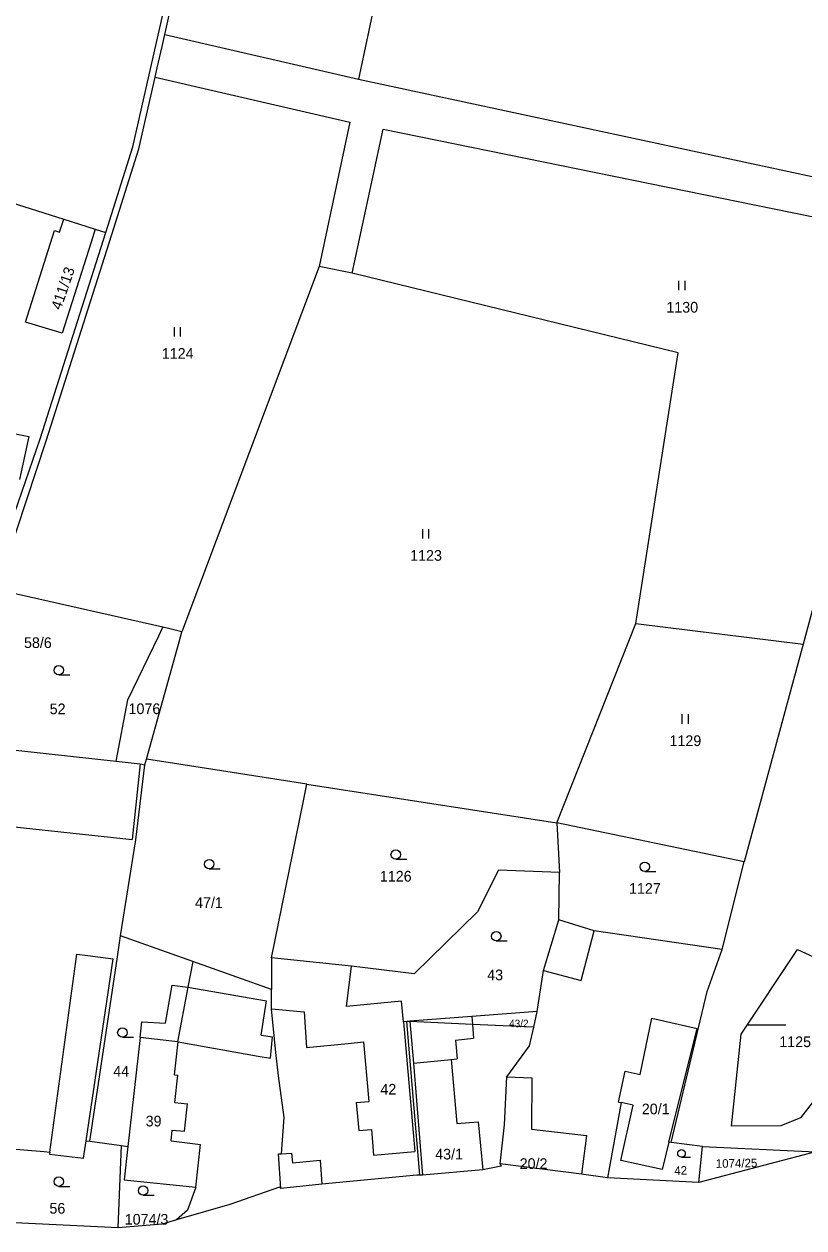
# Model space of a CAD drawing. Extents: x -746176 to -739709, y -1128407 to -1124482.
# Drawn here: x -742237.2 to -742113, y -1126052.3 to -1125860.6 of the extents above; entities that cross this region are included whole.
import ezdxf

# ---------------------------------------------------------------- set-up
doc = ezdxf.new("R2010")
doc.units = 0
for name, color, linetype in [('Hranice parcel', 7, 'Continuous'), ('Parcelní čísla', 7, 'Continuous'), ('Vnitřní kresba', 7, 'Continuous'), ('Značky kultur', 7, 'Continuous')]:
    doc.layers.add(name, color=color, linetype=linetype)

msp = doc.modelspace()

# ---------------------------------------------------------------- linework, layer by layer
at = {"layer": 'Hranice parcel'}
for p, q in [((-742144.45, -1125683.53), (-742183.95, -1125869.36)), ((-742214.78, -1125862.24), (-742205.45, -1125821.07)), ((-742214.78, -1125862.24), (-742183.95, -1125869.36)), ((-742183.95, -1125869.36), (-742094.09, -1125888.65)), ((-742251.35, -1125885.17), (-742230.88, -1125891.65)), ((-742230.88, -1125891.65), (-742225.86, -1125893.24)), ((-742225.86, -1125893.24), (-742224.19, -1125893.77)), ((-742190.21, -1125899.2), (-742212.05, -1125957.33)), ((-742184.93, -1125900.23), (-742190.21, -1125899.2)), ((-742110.2, -1125948.49), (-742113.1, -1125959.31)), ((-742215.07, -1125956.62), (-742241.51, -1125950.63)), ((-742152.36, -1125987.76), (-742139.76, -1125956.04)), ((-742139.76, -1125956.04), (-742113.1, -1125959.31)), ((-742113.1, -1125959.31), (-742122.54, -1125993.99)), ((-742246.94, -1125975.25), (-742222.55, -1125977.95)), ((-742217.96, -1125978.51), (-742217.71, -1125977.62)), ((-742192.16, -1125981.6), (-742152.36, -1125987.76)), ((-742122.54, -1125993.99), (-742152.36, -1125987.76)), ((-742152.36, -1125987.76), (-742151.94, -1125995.7)), ((-742126.05, -1126007.96), (-742122.54, -1125993.99)), ((-742152.03, -1126003.21), (-742151.94, -1125995.7)), ((-742210.31, -1126009.86), (-742221.81, -1126005.78)), ((-742197.78, -1126014.31), (-742210.31, -1126009.86)), ((-742197.79, -1126009.24), (-742197.78, -1126014.31)), ((-742174.18, -1126043.87), (-742176.24, -1126019.4)), ((-742156.03, -1126020.28), (-742155.5, -1126017.83)), ((-742156.03, -1126020.28), (-742165.79, -1126019.86)), ((-742226.7, -1126038.48), (-742221.69, -1126039.15)), ((-742129.13, -1126039.33), (-742134.12, -1126038.69)), ((-742222.2, -1126052.27), (-742221.69, -1126039.15)), ((-742221.69, -1126039.15), (-742220.66, -1126039.29)), ((-742129.74, -1126045.05), (-742129.13, -1126039.33)), ((-742111.14, -1126040.16), (-742129.74, -1126045.05)), ((-742129.13, -1126039.33), (-742111.14, -1126040.16)), ((-742148.42, -1126043.69), (-742161.35, -1126042.09)), ((-742144.3, -1126044.3), (-742148.42, -1126043.69)), ((-742129.74, -1126045.05), (-742144.3, -1126044.3))]:
    msp.add_line(p, q, dxfattribs=at)
for points in [[(-742224.19, -1125893.77), (-742219.86, -1125880.14), (-742206.44, -1125820.89)], [(-742216.33, -1125869.06), (-742215.99, -1125867.54), (-742215.21, -1125864.13), (-742214.78, -1125862.24)], [(-742241.51, -1125950.63), (-742233.66, -1125926.96), (-742223.23, -1125894.07), (-742218.91, -1125880.44), (-742217.69, -1125875.07), (-742216.33, -1125869.06)], [(-742216.33, -1125869.06), (-742185.29, -1125876.22), (-742190.21, -1125899.2)], [(-742184.93, -1125900.23), (-742180.03, -1125877.3), (-742095.09, -1125894.63)], [(-742225.86, -1125893.24), (-742226.52, -1125895.3), (-742231.11, -1125909.81), (-742236.97, -1125908.02), (-742232.36, -1125893.45), (-742231.54, -1125893.71), (-742230.88, -1125891.65)], [(-742239.87, -1125941.89), (-742234.61, -1125926.63), (-742224.19, -1125893.77)], [(-742139.76, -1125956.04), (-742133.02, -1125912.95), (-742184.93, -1125900.23)], [(-742261.6, -1125921.22), (-742236.44, -1125926.26), (-742237.93, -1125933.1)], [(-742222.55, -1125977.95), (-742220.67, -1125968.16), (-742215.73, -1125957.97), (-742215.07, -1125956.62)], [(-742217.71, -1125977.62), (-742212.49, -1125958.92), (-742212.05, -1125957.33)], [(-742212.05, -1125957.33), (-742213.99, -1125956.87), (-742215.07, -1125956.62)], [(-742222.55, -1125977.95), (-742218.7, -1125978.38), (-742217.96, -1125978.51)], [(-742221.81, -1126005.78), (-742219.41, -1125990.5), (-742217.96, -1125978.51)], [(-742192.16, -1125981.6), (-742212.57, -1125978.42), (-742217.71, -1125977.62)], [(-742197.79, -1126009.24), (-742192.7, -1125984.26), (-742192.16, -1125981.6)], [(-742151.94, -1125995.7), (-742161.62, -1125995.29), (-742165.01, -1126001.93), (-742175.08, -1126011.79), (-742185.07, -1126010.6)], [(-742155.5, -1126017.83), (-742154.46, -1126011.3), (-742152.03, -1126003.21)], [(-742126.05, -1126007.96), (-742146.39, -1126004.99), (-742152.03, -1126003.21)], [(-742226.7, -1126038.48), (-742222.39, -1126009.48), (-742221.81, -1126005.78)], [(-742134.12, -1126038.69), (-742128.4, -1126014.62), (-742126.05, -1126007.96)], [(-742102.49, -1126016.08), (-742109.85, -1126029.96), (-742113.56, -1126034.73), (-742116.68, -1126036.01), (-742124.54, -1126036.07), (-742122.99, -1126021.43), (-742114.02, -1126007.91), (-742106.36, -1126011.45), (-742102.49, -1126016.08)], [(-742210.31, -1126009.86), (-742211.09, -1126013.94), (-742212.75, -1126022.64), (-742218.71, -1126021.97), (-742220.66, -1126039.29)], [(-742185.07, -1126010.6), (-742196.8, -1126009.35), (-742197.79, -1126009.24)], [(-742176.24, -1126019.4), (-742176.77, -1126019.44), (-742177.07, -1126016.16), (-742185.84, -1126017), (-742185.07, -1126010.6)], [(-742196.32, -1126046.01), (-742196.68, -1126040.49), (-742196.21, -1126040.46), (-742195.76, -1126034.69), (-742196.68, -1126028.06), (-742197.1, -1126024.33), (-742197.78, -1126017.4), (-742197.78, -1126014.31)], [(-742155.5, -1126017.83), (-742165.88, -1126018.63), (-742175.74, -1126019.37), (-742176.24, -1126019.4)], [(-742165.79, -1126019.86), (-742175.74, -1126019.42), (-742176.24, -1126019.4)], [(-742160.34, -1126028.23), (-742156.69, -1126023.3), (-742156.03, -1126020.28)], [(-742161.35, -1126042.09), (-742160.66, -1126035.86), (-742160.34, -1126028.23)], [(-742160.34, -1126028.23), (-742156.31, -1126028.36), (-742156.37, -1126036.56), (-742147.63, -1126037.55), (-742148.42, -1126043.69)], [(-742134.12, -1126038.69), (-742134.51, -1126038.64), (-742135.58, -1126042.95), (-742142.18, -1126041.55), (-742140.2, -1126032.73), (-742142.09, -1126032.32), (-742144.3, -1126044.3)], [(-742240.91, -1126039.92), (-742239.93, -1126039.95), (-742239.83, -1126039.64), (-742234.01, -1126040.12), (-742233.11, -1126040.21), (-742233.15, -1126040.51), (-742227.7, -1126041.18), (-742227.29, -1126038.4), (-742226.7, -1126038.48)], [(-742222.2, -1126052.27), (-742242, -1126051.32), (-742240.91, -1126039.92)], [(-742220.66, -1126039.29), (-742221.25, -1126044.6), (-742209.84, -1126045.76), (-742211.16, -1126049.44), (-742212.94, -1126050.97)], [(-742161.35, -1126042.09), (-742161.2, -1126042.42), (-742164.15, -1126043.01), (-742173.72, -1126043.88), (-742174.18, -1126043.87)], [(-742174.18, -1126043.87), (-742174.65, -1126043.87), (-742189.75, -1126045.28), (-742196.32, -1126046.01)], [(-742196.32, -1126046.01), (-742196.53, -1126045.8), (-742204.43, -1126048.56), (-742212.94, -1126050.97)], [(-742212.94, -1126050.97), (-742215.19, -1126051.67), (-742222.2, -1126052.27)]]:
    msp.add_lwpolyline(points, dxfattribs=at)
at = {"layer": 'Vnitřní kresba'}
for p, q in [((-742218.7, -1125978.38), (-742220, -1125990.44)), ((-742240.74, -1125988.18), (-742220, -1125990.44)), ((-742148.47, -1126012.88), (-742146.39, -1126004.99)), ((-742233.11, -1126040.21), (-742228.77, -1126008.67)), ((-742228.77, -1126008.67), (-742227.02, -1126008.89)), ((-742227.29, -1126038.4), (-742222.99, -1126009.4)), ((-742227.02, -1126008.89), (-742222.99, -1126009.4)), ((-742154.46, -1126011.3), (-742148.47, -1126012.88)), ((-742214.69, -1126019.69), (-742213.59, -1126013.59)), ((-742213.59, -1126013.59), (-742211.09, -1126013.94)), ((-742211.09, -1126013.94), (-742198.6, -1126016.1)), ((-742199.41, -1126021.59), (-742198.6, -1126016.1)), ((-742197.78, -1126017.4), (-742192.59, -1126017.86)), ((-742218.71, -1126021.97), (-742218.42, -1126019.45)), ((-742218.42, -1126019.45), (-742214.69, -1126019.69)), ((-742192.59, -1126017.86), (-742192.2, -1126023.56)), ((-742176.77, -1126019.44), (-742174.94, -1126040.08)), ((-742175.74, -1126019.42), (-742175.19, -1126026.04)), ((-742165.88, -1126018.63), (-742165.79, -1126019.86)), ((-742139.09, -1126027.84), (-742137.21, -1126018.89)), ((-742137.21, -1126018.89), (-742130.02, -1126020.54)), ((-742165.79, -1126019.86), (-742165.62, -1126022.05)), ((-742134.51, -1126038.64), (-742130.02, -1126020.54)), ((-742213.26, -1126027.87), (-742212.63, -1126022.63)), ((-742212.75, -1126022.64), (-742212.63, -1126022.63)), ((-742212.63, -1126022.63), (-742199.91, -1126024.91)), ((-742199.41, -1126021.59), (-742197.64, -1126021.85)), ((-742197.95, -1126025.26), (-742197.64, -1126021.85)), ((-742192.2, -1126023.56), (-742185.56, -1126022.89)), ((-742185.56, -1126022.89), (-742183.15, -1126022.65)), ((-742183.15, -1126022.65), (-742182.29, -1126032.13)), ((-742168.51, -1126022.39), (-742165.62, -1126022.05)), ((-742168.51, -1126022.39), (-742168.22, -1126025.37)), ((-742199.91, -1126024.91), (-742197.95, -1126025.26)), ((-742169.17, -1126025.46), (-742168.22, -1126025.37)), ((-742175.19, -1126026.04), (-742169.17, -1126025.46)), ((-742175.19, -1126026.04), (-742173.72, -1126043.88)), ((-742169.17, -1126025.46), (-742168.27, -1126035.66)), ((-742213.26, -1126027.87), (-742212.72, -1126027.94)), ((-742213.19, -1126032.3), (-742212.72, -1126027.94)), ((-742142.53, -1126032.23), (-742141.46, -1126027.32)), ((-742141.46, -1126027.32), (-742139.09, -1126027.84)), ((-742213.19, -1126032.3), (-742211.19, -1126032.49)), ((-742211.62, -1126036.88), (-742211.19, -1126032.49)), ((-742184.31, -1126032.31), (-742182.29, -1126032.13)), ((-742184.31, -1126032.31), (-742183.89, -1126036.77)), ((-742142.53, -1126032.23), (-742142.09, -1126032.32)), ((-742213.77, -1126038.4), (-742213.6, -1126036.68)), ((-742213.6, -1126036.68), (-742211.62, -1126036.88)), ((-742183.89, -1126036.77), (-742181.89, -1126036.58)), ((-742181.89, -1126036.58), (-742181.52, -1126040.69)), ((-742168.27, -1126035.66), (-742164.88, -1126035.36)), ((-742164.88, -1126035.36), (-742164.15, -1126043.01)), ((-742213.77, -1126038.4), (-742209.07, -1126038.97)), ((-742209.84, -1126045.76), (-742209.07, -1126038.97)), ((-742196.21, -1126040.46), (-742194.61, -1126040.35)), ((-742194.61, -1126040.35), (-742194.47, -1126041.89)), ((-742181.52, -1126040.69), (-742174.94, -1126040.08)), ((-742194.47, -1126041.89), (-742190.03, -1126041.47)), ((-742190.03, -1126041.47), (-742189.75, -1126045.28))]:
    msp.add_line(p, q, dxfattribs=at)
at = {"layer": 'Značky kultur'}
for p, q in [((-742132.91, -1125902.97), (-742132.91, -1125901.47)), ((-742131.91, -1125902.97), (-742131.91, -1125901.47)), ((-742213.26, -1125910.33), (-742213.26, -1125908.83)), ((-742212.26, -1125910.33), (-742212.26, -1125908.83)), ((-742173.71, -1125942.49), (-742173.71, -1125940.99)), ((-742172.71, -1125942.49), (-742172.71, -1125940.99)), ((-742231.66, -1125964.22), (-742229.91, -1125964.22)), ((-742132.41, -1125971.99), (-742132.41, -1125970.49)), ((-742131.41, -1125971.99), (-742131.41, -1125970.49)), ((-742178.01, -1125993.57), (-742176.26, -1125993.57)), ((-742207.71, -1125995.08), (-742205.96, -1125995.08)), ((-742138.34, -1125995.51), (-742136.59, -1125995.51)), ((-742161.99, -1126006.58), (-742160.24, -1126006.58)), ((-742121.91, -1126019.93), (-742115.91, -1126019.93)), ((-742221.54, -1126021.92), (-742219.79, -1126021.92)), ((-742132.5, -1126041.02), (-742131.09, -1126041.02)), ((-742231.67, -1126045.65), (-742229.92, -1126045.65)), ((-742218.23, -1126047.07), (-742216.48, -1126047.07))]:
    msp.add_line(p, q, dxfattribs=at)
for centre, radius in [((-742231.66, -1125963.47), 0.75), ((-742178.01, -1125992.82), 0.75), ((-742207.71, -1125994.33), 0.75), ((-742138.34, -1125994.76), 0.75), ((-742161.99, -1126005.83), 0.75), ((-742221.54, -1126021.17), 0.75), ((-742132.5, -1126040.41), 0.607), ((-742231.67, -1126044.9), 0.75), ((-742218.23, -1126046.32), 0.75)]:
    msp.add_circle(centre, radius, dxfattribs=at)

# ---------------------------------------------------------------- texts
at = {"layer": 'Parcelní čísla'}
for s, height, rotation, p in [('411/13', 1.7, 71, (-742231.34, -1125906.2)), ('42', 1.37, 2, (-742133.63, -1126043.85)), ('1074/25', 1.37, 1, (-742127.03, -1126042.71))]:
    msp.add_text(s, height=height, rotation=rotation, dxfattribs=at).set_placement(p)
for s, height, p in [('1130', 1.7, (-742134.91, -1125906.52)), ('1124', 1.7, (-742215.26, -1125913.88)), ('1123', 1.7, (-742175.71, -1125946.04)), ('58/6', 1.7, (-742237.2, -1125959.93)), ('52', 1.7, (-742233.11, -1125970.47)), ('1076', 1.7, (-742220.55, -1125970.45)), ('1129', 1.7, (-742134.41, -1125975.54)), ('1126', 1.7, (-742180.53, -1125997.12)), ('1127', 1.7, (-742140.86, -1125999.07)), ('47/1', 1.7, (-742209.96, -1126001.33)), ('43', 1.7, (-742163.44, -1126012.83)), ('43/2', 1.19, (-742159.95, -1126020.31)), ('1125', 1.7, (-742116.93, -1126023.48)), ('44', 1.7, (-742222.99, -1126028.17)), ('42', 1.7, (-742180.45, -1126031.04)), ('20/1', 1.7, (-742138.82, -1126034.18)), ('39', 1.7, (-742217.83, -1126036.11)), ('43/1', 1.7, (-742171.72, -1126041.37)), ('20/2', 1.7, (-742158.27, -1126042.88)), ('56', 1.7, (-742233.15, -1126050)), ('1074/3', 1.7, (-742221.16, -1126051.75))]:
    msp.add_text(s, height=height, dxfattribs=at).set_placement(p)

doc.saveas('drawing.dxf')
